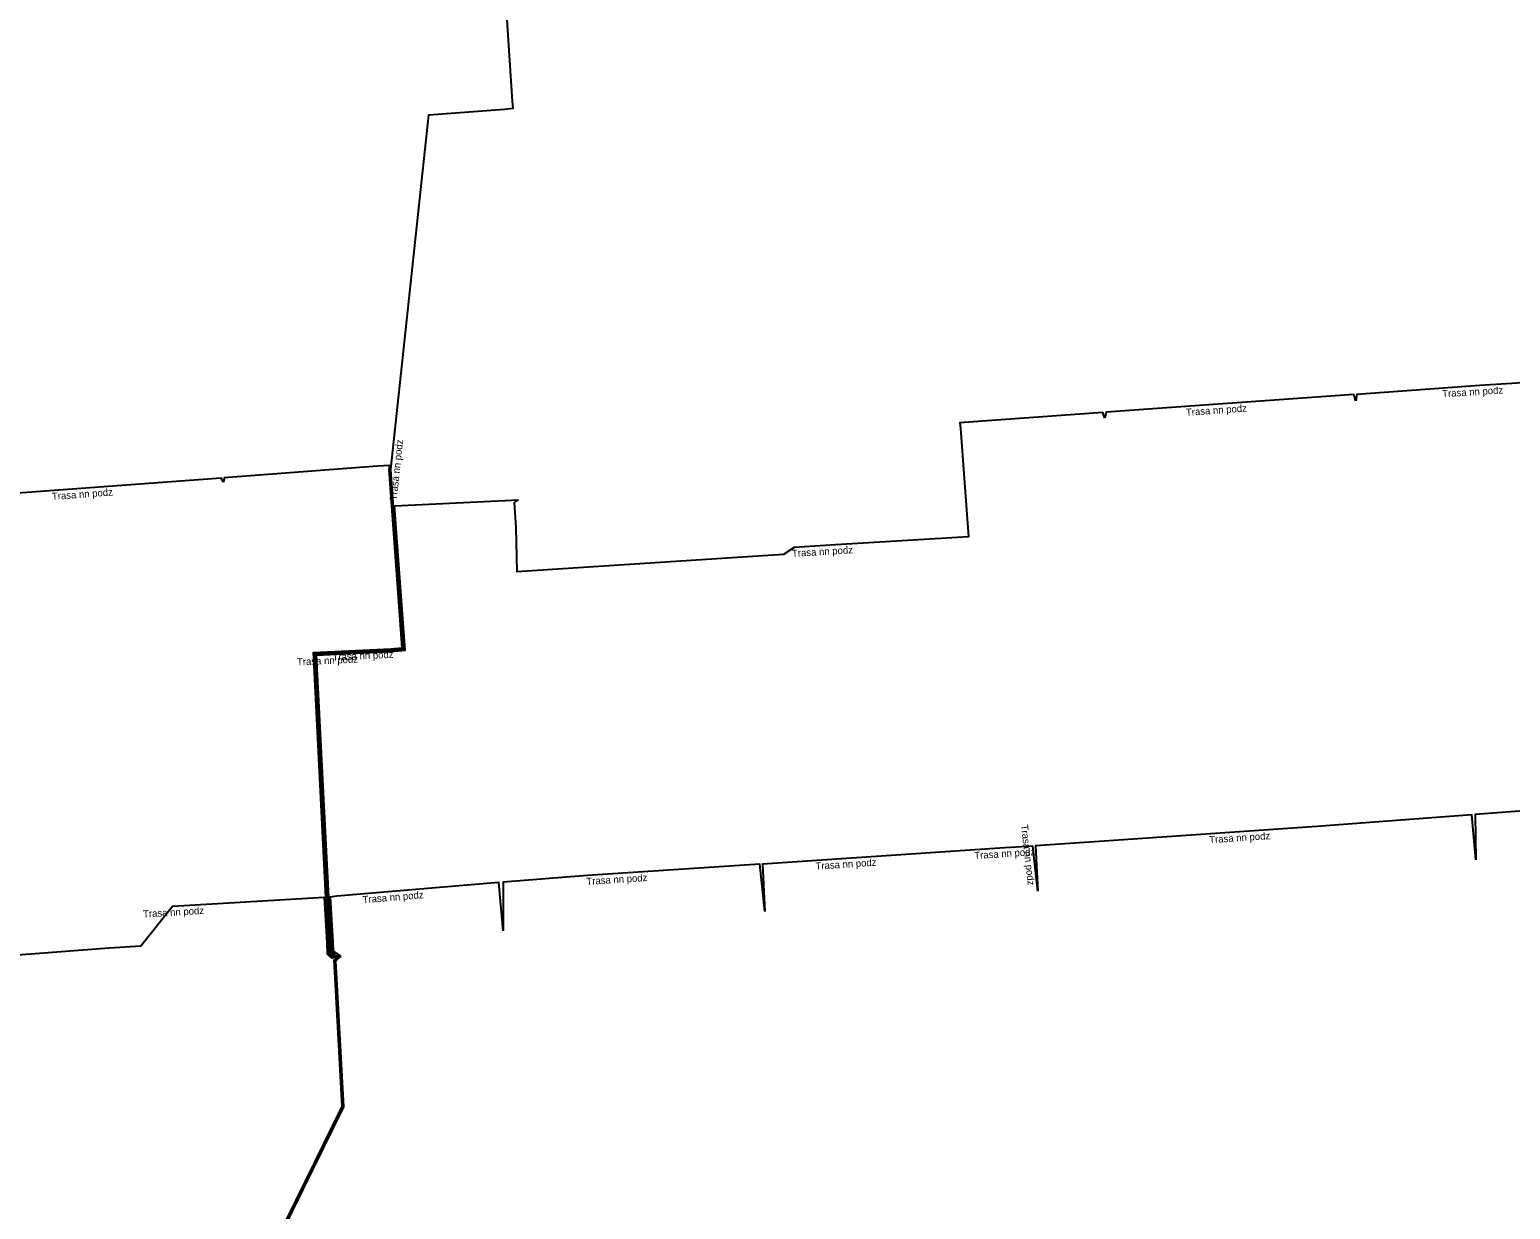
# Model space of a CAD drawing. Extents: x -873583 to -872966, y -1012951 to -1012536.
# Drawn here: x -873321.7 to -873218, y -1012723 to -1012640.4 of the extents above; entities that cross this region are included whole.
import ezdxf

# ---------------------------------------------------------------- set-up
doc = ezdxf.new("R2010")
doc.units = 0
doc.layers.add('Popiskový text - Ostatní atributy Trasy', color=7, linetype='Continuous')
doc.layers.add('Spojnice NN', color=7, linetype='Continuous')

msp = doc.modelspace()

# ---------------------------------------------------------------- linework, layer by layer
at = {"layer": 'Spojnice NN'}
for points in [[(-873299.89, -1012705.3), (-873300.31, -1012705.31), (-873300.62, -1012705.05), (-873300.65, -1012704.33), (-873300.83, -1012701.17), (-873301.7, -1012684.13), (-873296.38, -1012683.86), (-873295.48, -1012683.78), (-873295.53, -1012683), (-873296.39, -1012671.22), (-873293.71, -1012646.38), (-873288.42, -1012645.97), (-873287.8, -1012645.92), (-873287.85, -1012645.43), (-873288.55, -1012634.74), (-873289.09, -1012634.63)], [(-873210.31, -1012665.08), (-873210.42, -1012664.73), (-873220.08, -1012665.34), (-873228.71, -1012665.96), (-873228.78, -1012666.41)], [(-873228.78, -1012666.41), (-873228.91, -1012665.97), (-873246.26, -1012667.21), (-873246.35, -1012667.62)], [(-873246.35, -1012667.62), (-873246.49, -1012667.23), (-873256.21, -1012667.93), (-873256.52, -1012667.95), (-873256.48, -1012668.35), (-873255.92, -1012675.93), (-873265.22, -1012676.5), (-873268.12, -1012676.68), (-873268.86, -1012677.17), (-873287.21, -1012678.35), (-873287.52, -1012678.37), (-873287.61, -1012675.27), (-873287.71, -1012673.53), (-873287.44, -1012673.33)], [(-873308.11, -1012672.1), (-873308.26, -1012671.82), (-873325.69, -1012673.11), (-873325.8, -1012673.5)], [(-873299.89, -1012705.3), (-873300.42, -1012705.35), (-873300.72, -1012705.1), (-873300.75, -1012704.33), (-873300.93, -1012701.17), (-873301.8, -1012684.03), (-873296.39, -1012683.76), (-873295.59, -1012683.69), (-873296.49, -1012671.22), (-873296.46, -1012670.93), (-873297.31, -1012670.99), (-873308.05, -1012671.79), (-873308.11, -1012672.1)], [(-873299.89, -1012705.3), (-873300.22, -1012705.26), (-873300.52, -1012705), (-873300.55, -1012704.32), (-873300.73, -1012701.16), (-873301.59, -1012684.22), (-873296.37, -1012683.96), (-873295.37, -1012683.87), (-873296.11, -1012673.75), (-873287.44, -1012673.33)], [(-873202.63, -1012697.28), (-873203.08, -1012694.14), (-873213.88, -1012694.89), (-873220.41, -1012695.38), (-873220.36, -1012698.54)], [(-873220.36, -1012698.54), (-873220.64, -1012695.39), (-873231.52, -1012696.22), (-873246.41, -1012697.24), (-873251.21, -1012697.56), (-873251.05, -1012700.74)], [(-873253.37, -1012697.71), (-873270.34, -1012698.84), (-873270.17, -1012702.16)], [(-873251.41, -1012697.58), (-873253.37, -1012697.71)], [(-873251.05, -1012700.74), (-873251.41, -1012697.58)], [(-873270.17, -1012702.16), (-873270.54, -1012698.85), (-873282.59, -1012699.65), (-873288.52, -1012700.11), (-873288.51, -1012703.51)], [(-873288.51, -1012703.51), (-873288.81, -1012700.13), (-873300.15, -1012701.09), (-873300.63, -1012701.15), (-873300.45, -1012704.32), (-873300.42, -1012704.95), (-873299.89, -1012705.3)], [(-873299.89, -1012705.3), (-873300.48, -1012705.43), (-873300.82, -1012705.15), (-873300.85, -1012704.34), (-873301.03, -1012701.18), (-873311.68, -1012701.82), (-873313.89, -1012704.6), (-873316.11, -1012704.73), (-873323.15, -1012705.26), (-873323.24, -1012705.96)], [(-873298.55, -1012795.35), (-873298.45, -1012795.21), (-873299.78, -1012791.45), (-873305.53, -1012774.85), (-873308.74, -1012775.94), (-873311.94, -1012777.18), (-873312.45, -1012775.77), (-873316.6, -1012765.23), (-873319.74, -1012756.4), (-873299.78, -1012715.82), (-873300.34, -1012705.54), (-873299.89, -1012705.3)], [(-873298.55, -1012795.35), (-873298.36, -1012795.17), (-873299.69, -1012791.42), (-873305.47, -1012774.73), (-873308.78, -1012775.84), (-873311.88, -1012777.05), (-873312.35, -1012775.74), (-873316.51, -1012765.19), (-873319.64, -1012756.41), (-873299.68, -1012715.84), (-873300.24, -1012705.62), (-873299.89, -1012705.3)]]:
    msp.add_lwpolyline(points, dxfattribs=at)

# ---------------------------------------------------------------- texts
at = {"layer": 'Popiskový text - Ostatní atributy Trasy'}
for rotation, p in [(3.6617, (-873222.71, -1012666.16)), (4.0878, (-873240.66, -1012667.46)), (83.8308, (-873295.97, -1012673.39)), (4.2664, (-873320.1, -1012673.35)), (3.5168, (-873268.26, -1012677.34)), (2.8149, (-873302.94, -1012684.94)), (2.8157, (-873300.45, -1012684.61)), (276.6226, (-873252.24, -1012696.11)), (3.8994, (-873239.03, -1012697.39)), (3.8112, (-873255.49, -1012698.5)), (3.8102, (-873266.61, -1012699.24)), (3.7814, (-873282.66, -1012700.31)), (4.8338, (-873298.33, -1012701.59)), (3.4465, (-873313.72, -1012702.59))]:
    msp.add_text('Trasa nn podz', height=0.5, rotation=rotation, dxfattribs=at).set_placement(p)

doc.saveas('drawing.dxf')
